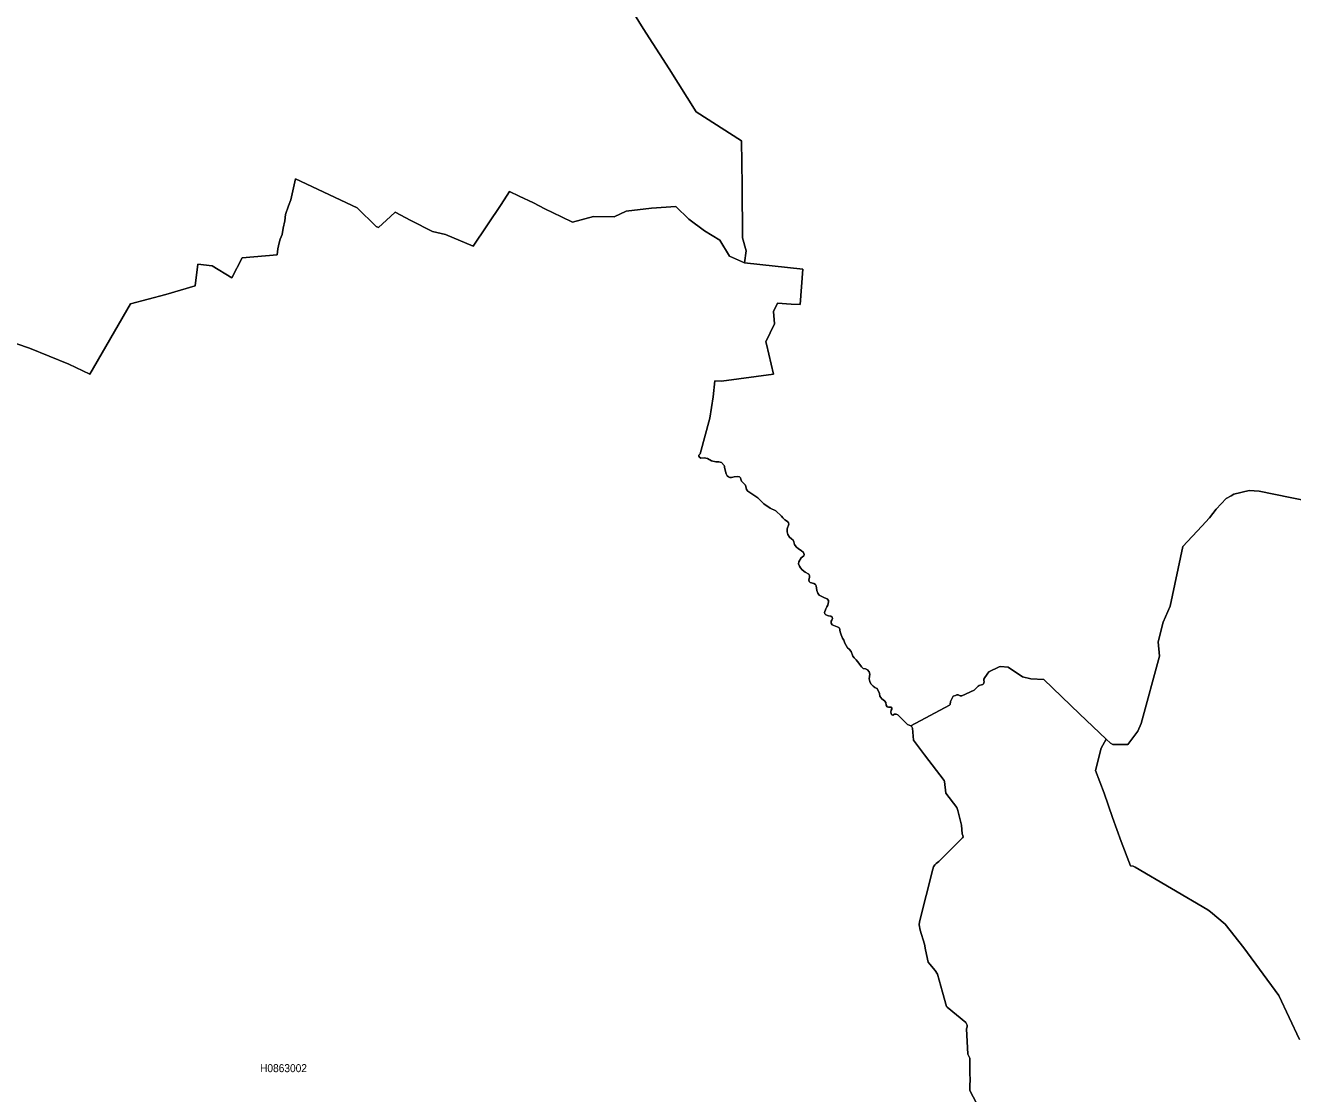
# Model space of a CAD drawing. Extents: x 369010 to 739155, y 6377141 to 6616555.
# Drawn here: x 486137 to 501969, y 6479662 to 6493007 of the extents above; entities that cross this region are included whole.
import ezdxf
from ezdxf.enums import TextEntityAlignment as Align

# ---------------------------------------------------------------- set-up
doc = ezdxf.new("R2010")
doc.units = 0
doc.header["$LTSCALE"] = 40
doc.layers.add('1', color=7, linetype='Continuous', lineweight=13)
doc.layers.add('2', color=7, linetype='Continuous')

msp = doc.modelspace()

# ---------------------------------------------------------------- linework, layer by layer
at = {"layer": '1'}
for points in [[(486032.12, 6489028.97), (486188.69, 6488973.2), (486678.91, 6488775.59), (486943.39, 6488648.98), (487449.5, 6489526.97), (487891.89, 6489645.47), (488257.82, 6489751.73), (488291.92, 6490023.32), (488472.15, 6490001.97), (488717.26, 6489851.86), (488844.87, 6490102.43), (489281.8, 6490142.65), (489289.74, 6490214.31), (489306.62, 6490289.78), (489322.01, 6490335.96), (489344.69, 6490394.05), (489357.6, 6490475.15), (489376.96, 6490564.52), (489388.88, 6490645.45), (489422.97, 6490753.69), (489454.91, 6490829.32), (489510.36, 6491088.84), (490283.59, 6490727.71), (490519.6, 6490494.51), (490547.57, 6490483.09), (490698.34, 6490617.48), (490756.77, 6490673.09), (490952.39, 6490569.65), (491225.31, 6490432.12), (491386.01, 6490394.55), (491732.41, 6490250.72), (492079.64, 6490767.92), (492187.38, 6490932.43), (492306.38, 6490875), (492485.95, 6490790.43), (492626.63, 6490715.62), (492835.33, 6490613.51), (492974.02, 6490547.14), (493233.04, 6490619.13), (493493.21, 6490616.49), (493642.83, 6490686), (493959.77, 6490725.22), (494264.62, 6490744.42), (494425.16, 6490585.54), (494620.79, 6490442.38), (494813.27, 6490324.87), (494932.93, 6490122.29), (495123.26, 6490040.2), (495142.46, 6490188.66), (495097.44, 6490352.34), (495090.99, 6491005.92), (495087.84, 6491291.08), (495085.36, 6491565.32), (494516.52, 6491928.93), (494181.54, 6492465.66), (493857.32, 6492968.13), (493537.23, 6493485.66)], [(493537.23, 6493485.66), (493857.32, 6492968.13), (494181.54, 6492465.66), (494516.52, 6491928.93), (495085.36, 6491565.32), (495087.84, 6491291.08), (495090.99, 6491005.92), (495097.44, 6490352.34), (495142.46, 6490188.66), (495123.26, 6490040.2), (495850.15, 6489962.08), (495817.88, 6489521.84), (495703.52, 6489523.66), (495533.21, 6489535.91), (495485.55, 6489433.3), (495495.15, 6489280.37), (495388.73, 6489054.29), (495397, 6489025), (495484.22, 6488651.29), (494832.47, 6488564.4), (494751.37, 6488565.23), (494731.68, 6488366.63), (494686.33, 6488101.98), (494567.5, 6487655.79), (494549.46, 6487636.26), (494552.77, 6487627.15), (494557.4, 6487611.1), (494574.12, 6487599.35), (494615.99, 6487605.47), (494659.35, 6487596.04), (494707.84, 6487565.42), (494761.3, 6487553.5), (494799.86, 6487553.5), (494832.14, 6487547.22), (494865.9, 6487510.14), (494873.02, 6487498.56), (494873.02, 6487484.49), (494893.37, 6487405.21), (494906.78, 6487380.06), (494920.68, 6487366.65), (494937.4, 6487357.55), (494958.42, 6487358.04), (494990.69, 6487368.8), (495033.39, 6487371.28), (495060.86, 6487366.82), (495070.79, 6487353.41), (495073.44, 6487336.2), (495085.03, 6487315.18), (495135.34, 6487262.38), (495147.92, 6487207.93), (495163.64, 6487188.57), (495199.56, 6487162.42), (495264.27, 6487122.2), (495288.6, 6487103.33), (495361.75, 6487028.69), (495440.36, 6486977.72), (495511.86, 6486944.45), (495583.69, 6486876.76), (495599.91, 6486855.24), (495624.9, 6486831.24), (495658.17, 6486809.56), (495669.92, 6486791.69), (495673.56, 6486774.97), (495656.35, 6486716.22), (495652.38, 6486679.15)], [(494751.37, 6488565.23), (494832.47, 6488564.4), (495484.22, 6488651.29), (495397, 6489025), (495388.73, 6489054.29), (495495.15, 6489280.37), (495485.55, 6489433.3), (495533.21, 6489535.91), (495703.52, 6489523.66), (495817.88, 6489521.84), (495850.15, 6489962.08), (495123.26, 6490040.2), (494932.93, 6490122.29), (494813.27, 6490324.87), (494620.79, 6490442.38), (494425.16, 6490585.54), (494264.62, 6490744.42), (493959.77, 6490725.22), (493642.83, 6490686), (493493.21, 6490616.49), (493233.04, 6490619.13), (492974.02, 6490547.14), (492835.33, 6490613.51), (492626.63, 6490715.62), (492485.95, 6490790.43), (492306.38, 6490875), (492187.38, 6490932.43), (492079.64, 6490767.92), (491732.41, 6490250.72), (491386.01, 6490394.55), (491225.31, 6490432.12), (490952.39, 6490569.65), (490756.77, 6490673.09), (490698.34, 6490617.48), (490547.57, 6490483.09), (490519.6, 6490494.51), (490283.59, 6490727.71), (489510.36, 6491088.84), (489454.91, 6490829.32), (489422.97, 6490753.69), (489388.88, 6490645.45), (489376.96, 6490564.52), (489357.6, 6490475.15), (489344.69, 6490394.05), (489322.01, 6490335.96), (489306.62, 6490289.78), (489289.74, 6490214.31), (489281.8, 6490142.65), (488844.87, 6490102.43), (488717.26, 6489851.86), (488472.15, 6490001.97), (488291.92, 6490023.32), (488257.82, 6489751.73), (487891.89, 6489645.47), (487449.5, 6489526.97), (486943.39, 6488648.98), (486678.91, 6488775.59), (486188.69, 6488973.2), (486032.12, 6489028.97)], [(496347.16, 6485353.46), (496329.29, 6485392.19), (496316.71, 6485431.58), (496307.27, 6485474.77), (496300.49, 6485483.71), (496238.59, 6485511.18), (496216.91, 6485520.12), (496204.83, 6485538.66), (496204.83, 6485562.49), (496212.94, 6485575.4), (496221.87, 6485598.41), (496216.91, 6485615.95), (496199.04, 6485628.03), (496172.55, 6485631.67), (496136.14, 6485643.75), (496124.89, 6485655.01), (496120.92, 6485673.38), (496139.29, 6485717.9), (496148.72, 6485744.88), (496160.31, 6485765.56), (496172.55, 6485807.77), (496170.73, 6485822.66), (496155.51, 6485845.01), (496120.42, 6485855.43), (496053.06, 6485890.85), (496039.16, 6485914.19), (496024.26, 6485946.63), (496017.97, 6486004.06), (496006.72, 6486022.1), (495986.53, 6486034.01), (495940.68, 6486048.91), (495928.6, 6486060.49), (495924.96, 6486079.86), (495933.07, 6486111.3), (495932.74, 6486133.31), (495923.64, 6486150.03), (495878.29, 6486175.52), (495839.73, 6486204.81), (495820.86, 6486228.64), (495808.61, 6486250.16), (495797.52, 6486281.61), (495799.67, 6486305.94), (495829.3, 6486354.26), (495860.75, 6486380.74), (495867.03, 6486397.79), (495858.92, 6486420.3), (495831.12, 6486446.28), (495794.38, 6486468.79), (495766.41, 6486494.78), (495747.54, 6486521.42), (495738.6, 6486556.34), (495728.34, 6486575.21), (495708.15, 6486591.93), (495684.65, 6486613.44), (495662.64, 6486647.54), (495652.38, 6486679.15), (495656.35, 6486716.22), (495673.56, 6486774.97), (495669.92, 6486791.69), (495658.17, 6486809.56), (495624.9, 6486831.24), (495599.91, 6486855.24), (495583.69, 6486876.76), (495511.86, 6486944.45), (495440.36, 6486977.72), (495361.75, 6487028.69), (495288.6, 6487103.33), (495264.27, 6487122.2), (495199.56, 6487162.42), (495163.64, 6487188.57), (495147.92, 6487207.93), (495135.34, 6487262.38), (495085.03, 6487315.18), (495073.44, 6487336.2), (495070.79, 6487353.41), (495060.86, 6487366.82), (495033.39, 6487371.28), (494990.69, 6487368.8), (494958.42, 6487358.04), (494937.4, 6487357.55), (494920.68, 6487366.65), (494906.78, 6487380.06), (494893.37, 6487405.21), (494873.02, 6487484.49), (494873.02, 6487498.56), (494865.9, 6487510.14), (494832.14, 6487547.22), (494799.86, 6487553.5), (494761.3, 6487553.5), (494707.84, 6487565.42), (494659.35, 6487596.04), (494615.99, 6487605.47), (494574.12, 6487599.35), (494557.4, 6487611.1), (494552.77, 6487627.15), (494549.46, 6487636.26), (494567.5, 6487655.79), (494686.33, 6488101.98), (494731.68, 6488366.63), (494751.37, 6488565.23)], [(497197.52, 6484255.34), (497683.94, 6484514.69), (497690.23, 6484523.46), (497695.85, 6484560.36), (497727.13, 6484629.21), (497758.08, 6484635.5), (497773.81, 6484642.12), (497789.53, 6484644.94), (497816.51, 6484631.2), (497837.36, 6484630.21), (497991.11, 6484701.7), (498039.94, 6484754), (498053.18, 6484760.96), (498083.63, 6484768.24), (498098.36, 6484773.7), (498108.95, 6484782.47), (498116.23, 6484804.65), (498112.1, 6484821.03), (498111.27, 6484839.24), (498124.51, 6484862.41), (498175.15, 6484932.75), (498301.6, 6484992.83), (498320.63, 6484996.63), (498415.13, 6484990.67), (498594.37, 6484869.69), (498696.49, 6484843.71), (498862.66, 6484835.27), (499308.03, 6484408.43), (499639.7, 6484091.16), (499692.49, 6484039.03), (499720.96, 6484022.81), (499910.13, 6484022.97), (500037.07, 6484191.29), (500078.78, 6484287.78), (500305.85, 6485127.22), (500289.3, 6485307.12), (500353.35, 6485553.06), (500439.74, 6485752.99), (500598.46, 6486496.1), (500833.48, 6486750.48), (500928.48, 6486856.4), (501013.55, 6486964.64), (501136.68, 6487094.89), (501199.57, 6487131.97), (501236.31, 6487149.18), (501427.97, 6487194.86), (501552.59, 6487188.4), (501939.04, 6487109.13), (502350.65, 6487027.04)], [(501939.04, 6487109.13), (501552.59, 6487188.4), (501427.97, 6487194.86), (501236.31, 6487149.18), (501199.57, 6487131.97), (501136.68, 6487094.89), (501013.55, 6486964.64), (500928.48, 6486856.4), (500833.48, 6486750.48)], [(502350.65, 6487027.04), (501939.04, 6487109.13)], [(500833.48, 6486750.48), (500598.46, 6486496.1), (500439.74, 6485752.99), (500353.35, 6485553.06), (500289.3, 6485307.12), (500305.85, 6485127.22), (500078.78, 6484287.78), (500037.07, 6484191.29), (499910.13, 6484022.97), (499720.96, 6484022.81), (499692.49, 6484039.03), (499639.7, 6484091.16), (499577.47, 6483979.28), (499507.13, 6483699.41), (499612.56, 6483415.57), (499720.46, 6483111.05), (499828.37, 6482810.82), (499943.23, 6482508.61), (499976.33, 6482501.83), (499999.83, 6482491.56), (500908.78, 6481959.63), (500944.53, 6481935.14), (501125.92, 6481778.57), (501357.96, 6481481.99), (501796.38, 6480887), (502056.39, 6480339.85)], [(495652.38, 6486679.15), (495662.64, 6486647.54), (495684.65, 6486613.44), (495708.15, 6486591.93), (495728.34, 6486575.21), (495738.6, 6486556.34), (495747.54, 6486521.42), (495766.41, 6486494.78), (495794.38, 6486468.79), (495831.12, 6486446.28), (495858.92, 6486420.3), (495867.03, 6486397.79), (495860.75, 6486380.74), (495829.3, 6486354.26), (495799.67, 6486305.94), (495797.52, 6486281.61), (495808.61, 6486250.16), (495820.86, 6486228.64), (495839.73, 6486204.81), (495878.29, 6486175.52), (495923.64, 6486150.03), (495932.74, 6486133.31), (495933.07, 6486111.3), (495924.96, 6486079.86), (495928.6, 6486060.49), (495940.68, 6486048.91), (495986.53, 6486034.01), (496006.72, 6486022.1), (496017.97, 6486004.06), (496024.26, 6485946.63), (496039.16, 6485914.19), (496053.06, 6485890.85), (496120.42, 6485855.43), (496155.51, 6485845.01), (496170.73, 6485822.66), (496172.55, 6485807.77), (496160.31, 6485765.56), (496148.72, 6485744.88), (496139.29, 6485717.9), (496120.92, 6485673.38), (496124.89, 6485655.01), (496136.14, 6485643.75), (496172.55, 6485631.67), (496199.04, 6485628.03), (496216.91, 6485615.95), (496221.87, 6485598.41), (496212.94, 6485575.4), (496204.83, 6485562.49), (496204.83, 6485538.66), (496216.91, 6485520.12), (496238.59, 6485511.18), (496300.49, 6485483.71), (496307.27, 6485474.77), (496316.71, 6485431.58), (496329.29, 6485392.19), (496347.16, 6485353.46), (496362.06, 6485328.3), (496374.63, 6485289.58), (496409.72, 6485231.65), (496430.74, 6485214.6), (496455.4, 6485184.98), (496472.94, 6485128.37), (496489.66, 6485105.04), (496515.64, 6485080.21), (496551.23, 6485037.84), (496581.18, 6484994.65), (496603.69, 6484973.13), (496633.81, 6484967.17), (496659.47, 6484955.09), (496679.99, 6484929.44), (496687.77, 6484902.96), (496679.99, 6484845.03), (496686.28, 6484811.27), (496699.35, 6484781.15), (496728.65, 6484753.34), (496749.17, 6484737.62), (496765.39, 6484729.01), (496780.62, 6484723.22), (496806.27, 6484661.49), (496813.88, 6484629.05), (496835.07, 6484594.95), (496868.66, 6484569.8), (496885.71, 6484548.61), (496892.99, 6484516.34), (496904.58, 6484493.67), (496921.29, 6484489.2), (496953.07, 6484489.2), (496962.51, 6484479.27), (496962.17, 6484464.04), (496953.57, 6484452.29), (496948.6, 6484428.46), (496953.07, 6484410.09), (496958.7, 6484399.33), (496963.5, 6484393.04), (496974.42, 6484390.56), (496996.1, 6484402.47), (497014.14, 6484402.97), (497038.64, 6484393.21), (497158.63, 6484273.21), (497197.52, 6484255.34)], [(498146.52, 6479306.44), (497935.83, 6479700.17), (497934.51, 6479744.69), (497940.14, 6479853.93), (497935.83, 6479898.45), (497934.84, 6480103.84), (497911.01, 6480155.14), (497895.29, 6480471.42), (497902.9, 6480498.57), (497901.57, 6480518.26), (497886.18, 6480549.54), (497655.14, 6480740.53), (497646.86, 6480752.12), (497593.74, 6480928.05), (497530.35, 6481155.78), (497504.53, 6481198.65), (497437.01, 6481279.08), (497414.5, 6481302.91), (497382.39, 6481460.31), (497371.8, 6481527.34), (497314.2, 6481703.77), (497304.6, 6481770.46), (497307.75, 6481808.86), (497474.91, 6482467.4), (497484.34, 6482497.36), (497498.41, 6482519.53), (497514.96, 6482537.08), (497547.73, 6482560.25), (497842.66, 6482857.49), (497852.42, 6482870.9), (497849.61, 6482887.12), (497838.52, 6482906.81), (497831.57, 6483017.21), (497787.54, 6483197.27), (497771.99, 6483236.99), (497635.61, 6483415.57), (497619.06, 6483560.22), (497614.92, 6483574.13), (497370.14, 6483893.05), (497232.44, 6484078.25), (497219.04, 6484226.71), (497211.75, 6484243.59), (497197.52, 6484255.34), (497158.63, 6484273.21), (497038.64, 6484393.21), (497014.14, 6484402.97), (496996.1, 6484402.47), (496974.42, 6484390.56), (496963.5, 6484393.04), (496958.7, 6484399.33), (496953.07, 6484410.09), (496948.6, 6484428.46), (496953.57, 6484452.29), (496962.17, 6484464.04), (496962.51, 6484479.27), (496953.07, 6484489.2), (496921.29, 6484489.2), (496904.58, 6484493.67), (496892.99, 6484516.34), (496885.71, 6484548.61), (496868.66, 6484569.8), (496835.07, 6484594.95), (496813.88, 6484629.05), (496806.27, 6484661.49), (496780.62, 6484723.22), (496765.39, 6484729.01), (496749.17, 6484737.62), (496728.65, 6484753.34), (496699.35, 6484781.15), (496686.28, 6484811.27), (496679.99, 6484845.03), (496687.77, 6484902.96), (496679.99, 6484929.44), (496659.47, 6484955.09), (496633.81, 6484967.17), (496603.69, 6484973.13), (496581.18, 6484994.65), (496551.23, 6485037.84), (496515.64, 6485080.21), (496489.66, 6485105.04), (496472.94, 6485128.37), (496455.4, 6485184.98), (496430.74, 6485214.6), (496409.72, 6485231.65), (496374.63, 6485289.58), (496362.06, 6485328.3), (496347.16, 6485353.46)], [(502056.39, 6480339.85), (501796.38, 6480887), (501357.96, 6481481.99), (501125.92, 6481778.57), (500944.53, 6481935.14), (500908.78, 6481959.63), (499999.83, 6482491.56), (499976.33, 6482501.83), (499943.23, 6482508.61), (499828.37, 6482810.82), (499720.46, 6483111.05), (499612.56, 6483415.57), (499507.13, 6483699.41), (499577.47, 6483979.28), (499639.7, 6484091.16), (499308.03, 6484408.43), (498862.66, 6484835.27), (498696.49, 6484843.71), (498594.37, 6484869.69), (498415.13, 6484990.67), (498320.63, 6484996.63), (498301.6, 6484992.83), (498175.15, 6484932.75), (498124.51, 6484862.41), (498111.27, 6484839.24), (498112.1, 6484821.03), (498116.23, 6484804.65), (498108.95, 6484782.47), (498098.36, 6484773.7), (498083.63, 6484768.24), (498053.18, 6484760.96), (498039.94, 6484754), (497991.11, 6484701.7), (497837.36, 6484630.21), (497816.51, 6484631.2), (497789.53, 6484644.94), (497773.81, 6484642.12), (497758.08, 6484635.5), (497727.13, 6484629.21), (497695.85, 6484560.36), (497690.23, 6484523.46), (497683.94, 6484514.69), (497197.52, 6484255.34)], [(497197.52, 6484255.34), (497211.75, 6484243.59), (497219.04, 6484226.71), (497232.44, 6484078.25), (497370.14, 6483893.05), (497614.92, 6483574.13), (497619.06, 6483560.22), (497635.61, 6483415.57), (497771.99, 6483236.99), (497787.54, 6483197.27), (497831.57, 6483017.21), (497838.52, 6482906.81), (497849.61, 6482887.12), (497852.42, 6482870.9), (497842.66, 6482857.49), (497547.73, 6482560.25), (497514.96, 6482537.08), (497498.41, 6482519.53), (497484.34, 6482497.36), (497474.91, 6482467.4), (497307.75, 6481808.86), (497304.6, 6481770.46), (497314.2, 6481703.77), (497371.8, 6481527.34), (497382.39, 6481460.31), (497414.5, 6481302.91), (497437.01, 6481279.08), (497504.53, 6481198.65), (497530.35, 6481155.78), (497593.74, 6480928.05), (497646.86, 6480752.12), (497655.14, 6480740.53), (497886.18, 6480549.54), (497901.57, 6480518.26), (497902.9, 6480498.57), (497895.29, 6480471.42), (497911.01, 6480155.14), (497934.84, 6480103.84), (497935.83, 6479898.45), (497940.14, 6479853.93), (497934.51, 6479744.69), (497935.83, 6479700.17), (498146.52, 6479306.44)]]:
    msp.add_lwpolyline(points, dxfattribs=at)

# ---------------------------------------------------------------- texts
at = {"layer": '2', "width": 0.95}
msp.add_text('H0863002', height=100, dxfattribs=at).set_placement((489362.32, 6479930.39), align=Align.CENTER)

doc.saveas('drawing.dxf')
